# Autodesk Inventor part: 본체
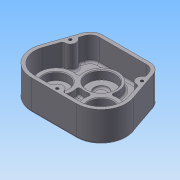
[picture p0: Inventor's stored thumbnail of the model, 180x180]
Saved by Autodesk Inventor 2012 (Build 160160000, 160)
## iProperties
Created: 2014-12
Part Number: 본체
Material: 알루미늄-6061
Document SubType Name: Modeling
Designer: User11
Density: 2.71 g/cm^3
Mass: 613.436 g
Surface Area: 665.18 cm^2
Volume: 226.36 cm^3
Author: User11
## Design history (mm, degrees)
sketch "스케치1"
  geometry: L1 (-47, 36)-(47, 36); L2 (47, 36)-(66.565, -20.803); L3 (-47, 36)-(-66.565, -20.803); L4 (-32.527, -68.527)-(32.527, -68.527); L5 (-32.527, -32.527)-(0, 0); L6 (0, 0)-(32.527, -32.527); A1 r 36 centre (-32.527, -32.527) between (-66.565, -20.803) and (-32.527, -68.527); A2 r 36 centre (32.527, -32.527) between (32.527, -68.527) and (66.565, -20.803)
  constraints: 12 end point, 4 point on circle, 4 tangent, 2 centre point, 2 horizontal, 1 equal length, 1 horizontal alignment
  dimensions: "d0" = 36 distance from line of L5.end L1; "d1" = 47 horizontal distance of L5.end L1.start; "d2" = 94 distance of L1.start L1.end; "d3" = 36 radius of A2; "d4" = 90 deg angle of L6 L5; "d6" = 46 distance of L5.start L5.end
extrude "돌출1" new body sketch "스케치1" distance "d7" = 44; taper "d8" = 0 deg
fillet "모깎기1" dims "d9" = 18
feature "쉘1" dims "d10" = 5
feature "두껍게 하기1" dims "d11" = 5, "d12" = 5
sketch "스케치2"
  geometry: A1 r 31 centre (1.635, -63.527) between (-27.675, -53.432) and (1.635, -94.527) reference; A2 r 31 centre (66.689, -63.527) between (66.689, -94.527) and (95.999, -53.432) reference; A3 r 24 centre (1.635, -63.527) between (13.051, -42.416) and (22.746, -52.111); A4 r 24 centre (66.689, -63.527) between (45.578, -52.111) and (55.273, -42.416); A5 r 24 centre (34.162, -31) between (22.746, -52.111) and (45.578, -52.111); A6 r 24 centre (34.162, -31) between (55.273, -42.416) and (13.051, -42.416); 1 further point
  constraints: 8 point on circle, 4 centre point, 3 coincident, 1 concentric
  dimensions: "d14" = 48 diameter of A3; "d15" = 48 diameter of A4; "d16" = 24 radius of A6
extrude "돌출2" join sketch "스케치2" distance "d17" = 11; taper "d18" = 0 deg
sketch "스케치3"
  geometry: C1 r 20 at (-32.527, -32.527); C2 r 20 at (32.527, -32.527); A1 r 36 centre (-32.527, -32.527) between (-66.565, -20.803) and (-32.527, -68.527) reference; A2 r 36 centre (32.527, -32.527) between (32.527, -68.527) and (66.565, -20.803) reference; 1 further point
  constraints: 2 centre point, 2 coincident, 1 equal radius
  dimensions: "d19" = 40 diameter of C1
extrude "돌출3" join sketch "스케치3" distance "d20" = 7; taper "d21" = -10 deg
sketch "스케치4"
  geometry: L1 (46.453, 22.233)-(61.837, -22.432) reference; L2 (32.527, -63.527)-(-32.527, -63.527) reference; L3 (-61.837, -22.432)-(-46.453, 22.233) reference; L4 (-34.162, 36)-(34.162, 36) reference; L5 (-61.837, -22.432)-(-46.453, 22.233) reference; L6 (-34.162, 31)-(34.162, 31) reference; A1 r 8 centre (-51.7, 7) between (-54.305, -0.564) and (-49.095, 14.564); A2 r 8 centre (51.7, 7) between (49.095, 14.564) and (54.305, -0.564); A3 r 8 centre (0, -63.527) between (8, -63.527) and (-8, -63.527); 2 further points
  constraints: 8 point on line, 6 point on circle, 3 centre point, 2 equal radius, 2 midpoint, 2 vertical alignment, 1 horizontal alignment
  dimensions: "d22" = 16 diameter of A1; "d23" = 29 distance from line of A1.centre L4
extrude "돌출4" join sketch "스케치4" stored distance "d24" = 7; taper "d25" = 0 deg
extrude "돌출5" join sketch "스케치4" stored distance "d26" = 7; taper "d27" = 0 deg
extrude "돌출6" join sketch "스케치4" stored distance "d28" = 7; taper "d29" = 0 deg
fillet "모깎기2" dims "d30" = 3
fillet "모깎기3" dims "d31" = 3
hole "구멍1" diameter "d34" = 15.5; stored, may be unused: countersink angle "d38" = 90 deg, drill point angle "d40" = 118 deg; dims "d32" = 10, "d33" = 10, "d35" = 6, "d36" = 4, "d37" = 2, "d39" = 8
hole "구멍2" diameter "d43" = 15.5; stored, may be unused: countersink angle "d47" = 90 deg, drill point angle "d49" = 118 deg; dims "d41" = 10, "d42" = 10, "d44" = 6, "d45" = 4, "d46" = 2, "d48" = 8
hole "구멍3" diameter "d52" = 35; stored, may be unused: countersink angle "d56" = 90 deg, drill point angle "d58" = 0 deg; dims "d50" = 10, "d51" = 10, "d53" = 6, "d54" = 4, "d55" = 2, "d57" = 11
hole "구멍4" diameter "d61" = 35; stored, may be unused: countersink angle "d65" = 90 deg, drill point angle "d67" = 0 deg; dims "d62" = 6, "d63" = 4, "d64" = 2, "d66" = 11, "d68" = 10, "d69" = 10
hole "구멍5" diameter "d72" = 30; stored, may be unused: countersink angle "d76" = 90 deg, drill point angle "d78" = 0 deg; dims "d70" = 10, "d71" = 10, "d73" = 6, "d74" = 4, "d75" = 2, "d77" = 7
hole "구멍6" diameter "d81" = 30; stored, may be unused: countersink angle "d85" = 90 deg, drill point angle "d87" = 0 deg; dims "d82" = 6, "d83" = 4, "d84" = 2, "d86" = 7, "d88" = 10, "d89" = 10
hole "구멍7" diameter "d92" = 40; stored, may be unused: countersink angle "d96" = 90 deg, drill point angle "d98" = 0 deg; dims "d90" = 10, "d91" = 10, "d93" = 6, "d94" = 4, "d95" = 2, "d97" = 12
hole "구멍8" diameter "d101" = 20; stored, may be unused: countersink angle "d105" = 90 deg, drill point angle "d107" = 0 deg; dims "d99" = 10, "d100" = 10, "d102" = 6, "d103" = 4, "d104" = 2, "d106" = 3
chamfer "모따기1" distance "d108" = 1; stored, may be unused: second distance "d109" = 2, angle "d110" = 45 deg
fillet "모깎기4" dims "d111" = 0.3, "d112" = 0.1, "d113" = 3
hole "구멍9" diameter "d116" = 4.134; stored, may be unused: countersink angle "d120" = 90 deg, drill point angle "d122" = 118 deg; dims "d114" = 10, "d115" = 10, "d117" = 20, "d118" = 4, "d119" = 2, "d121" = 23
hole "구멍10" diameter "d125" = 4.134; stored, may be unused: countersink angle "d129" = 90 deg, drill point angle "d131" = 118 deg; dims "d123" = 10, "d124" = 10, "d126" = 20, "d127" = 4, "d128" = 2, "d130" = 23
hole "구멍11" diameter "d134" = 4.134; stored, may be unused: countersink angle "d138" = 90 deg, drill point angle "d140" = 118 deg; dims "d132" = 10, "d133" = 10, "d135" = 20, "d136" = 4, "d137" = 2, "d139" = 23
sketch "스케치5"
  geometry: L1 (34.162, 36)-(-34.162, 36) reference; 2 further points
  constraints: 1 vertical alignment, 1 other
  dimensions: "d141" = 30 distance from line of L1 point (0, 6)
feature "엠보싱1" sketch "스케치5" dims "d0" = 36, "d1" = 47, "d2" = 94, "d3" = 36, "d4" = 90 deg, "d6" = 46, "d142" = 1, "d143" = 0
node "솔리드1"
other parameters: "d13" = 48
